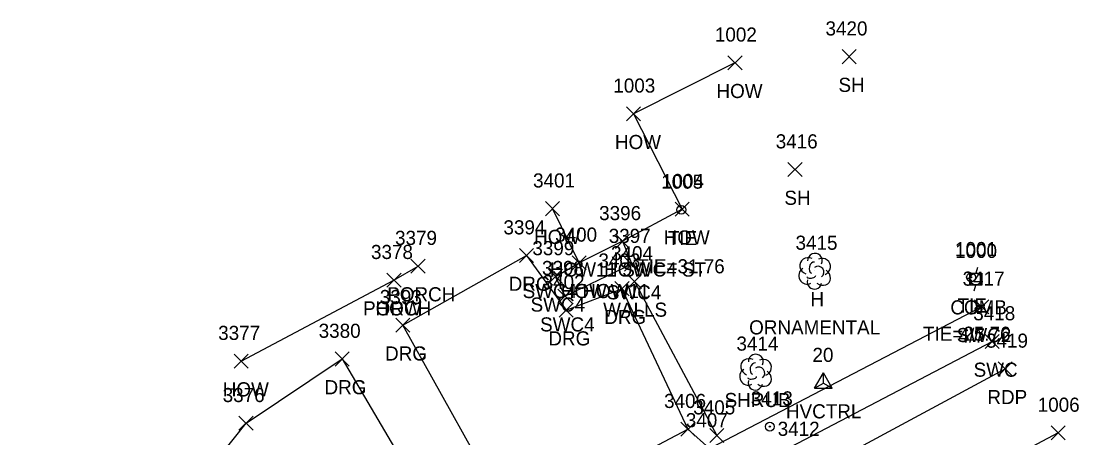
# Model space of a CAD drawing. Extents: x 1477930 to 1480780, y 774090 to 784647.
# Drawn here: x 1479868.8 to 1480018.8, y 775005.2 to 775064.2 of the extents above; entities that cross this region are included whole.
import ezdxf

# ---------------------------------------------------------------- set-up
doc = ezdxf.new("R2010")
doc.units = 0
for name, color, linetype in [('C_A', 7, 'Continuous'), ('C_C', 7, 'Continuous'), ('C_I', 7, 'Continuous'), ('CBP', 7, 'Continuous'), ('CPSM', 7, 'Continuous'), ('L_A', 7, 'Continuous'), ('L_C', 7, 'Continuous'), ('L_I', 7, 'Continuous'), ('L_TIC', 7, 'Continuous'), ('LBC', 7, 'Continuous'), ('LBF', 7, 'Continuous'), ('LSH', 7, 'Continuous'), ('LTD', 7, 'Continuous'), ('LWS', 7, 'Continuous'), ('P_A', 7, 'Continuous'), ('P_I', 7, 'Continuous'), ('P_TIC', 7, 'Continuous'), ('PET', 7, 'Continuous'), ('PRC', 7, 'Continuous'), ('R_A', 7, 'Continuous'), ('R_I', 7, 'Continuous'), ('R_TIC', 7, 'Continuous'), ('RDG', 7, 'Continuous'), ('RDP', 7, 'Continuous'), ('RSW', 7, 'Continuous'), ('U_A', 7, 'Continuous'), ('U_C', 7, 'Continuous'), ('U_I', 7, 'Continuous'), ('UP', 7, 'Continuous'), ('UWV', 7, 'Continuous')]:
    doc.layers.add(name, color=color, linetype=linetype)

msp = doc.modelspace()

# ---------------------------------------------------------------- linework, layer by layer
at = {"layer": 'CBP'}
for centre, radius in [((1479962.44, 775037.49), 0.625), ((1479962.44, 775037.49), 0.0833), ((1480003.53, 775027.93), 0.625), ((1480003.53, 775027.93), 0.0833)]:
    msp.add_circle(centre, radius, dxfattribs=at)
at = {"layer": 'CPSM'}
for p, q in [((1479981.34, 775012.21), (1479982.59, 775014.37)), ((1479983.84, 775012.21), (1479982.59, 775014.37)), ((1479982.59, 775012.93), (1479982.59, 775014.37)), ((1479981.34, 775012.21), (1479982.59, 775012.93)), ((1479981.34, 775012.21), (1479983.84, 775012.21)), ((1479982.59, 775012.93), (1479982.59, 775012.93)), ((1479982.59, 775012.93), (1479983.84, 775012.21))]:
    msp.add_line(p, q, dxfattribs=at)
at = {"layer": 'L_TIC'}
for points in [[(1479985.24, 775058.21), (1479987.24, 775060.21)], [(1479987.24, 775058.21), (1479985.24, 775060.21)], [(1479969.05, 775057.34), (1479971.05, 775059.34)], [(1479971.05, 775057.34), (1479969.05, 775059.34)], [(1479954.65, 775050.11), (1479956.65, 775052.11)], [(1479956.65, 775050.11), (1479954.65, 775052.11)], [(1479977.57, 775042.2), (1479979.57, 775044.2)], [(1479979.57, 775042.2), (1479977.57, 775044.2)], [(1479943.19, 775036.66), (1479945.19, 775038.66)], [(1479945.19, 775036.66), (1479943.19, 775038.66)], [(1479961.55, 775036.58), (1479963.55, 775038.58)], [(1479963.55, 775036.58), (1479961.55, 775038.58)], [(1479961.55, 775036.58), (1479963.55, 775038.58)], [(1479963.55, 775036.58), (1479961.55, 775038.58)], [(1479953.1, 775032.03), (1479955.1, 775034.03)], [(1479955.1, 775032.03), (1479953.1, 775034.03)], [(1479924.11, 775028.52), (1479926.11, 775030.52)], [(1479926.11, 775028.52), (1479924.11, 775030.52)], [(1479946.97, 775028.98), (1479948.97, 775030.98)], [(1479948.97, 775028.98), (1479946.97, 775030.98)], [(1479920.7, 775026.52), (1479922.7, 775028.52)], [(1479922.7, 775026.52), (1479920.7, 775028.52)], [(1479920.7, 775026.52), (1479922.7, 775028.52)], [(1479922.7, 775026.52), (1479920.7, 775028.52)], [(1479954.82, 775026.34), (1479956.82, 775028.34)], [(1479956.82, 775026.34), (1479954.82, 775028.34)], [(1479899.03, 775015.05), (1479901.03, 775017.05)], [(1479901.03, 775015.05), (1479899.03, 775017.05)], [(1479966.48, 775004.49), (1479968.48, 775006.49)], [(1479968.48, 775004.49), (1479966.48, 775006.49)]]:
    msp.add_lwpolyline(points, dxfattribs=at)
at = {"layer": 'LBC'}
for points in [[(1479970.05, 775058.34), (1479955.65, 775051.11), (1479962.55, 775037.58)], [(1479962.55, 775037.58), (1479954.1, 775033.03), (1479947.97, 775029.98), (1479944.19, 775037.66)], [(1479900.03, 775016.05), (1479921.7, 775027.52)]]:
    msp.add_lwpolyline(points, dxfattribs=at)
at = {"layer": 'LBF'}
msp.add_lwpolyline([(1479921.7, 775027.52), (1479925.11, 775029.52)], dxfattribs=at)
at = {"layer": 'LSH'}
msp.add_line((1479972.95, 775014.53), (1479972.95, 775014.53), dxfattribs=at)
msp.add_line((1479972.95, 775014.53), (1479972.95, 775014.53), dxfattribs=at)
msp.add_arc((1479973, 775015.97), 1.05, 335.5272, 180.9563, dxfattribs=at)
for centre, major_axis, ratio, start_param, end_param in [((1479972.16, 775015.2), (1.21, -0.51), 0.895232, 1.570796, 4.712389), ((1479972.74, 775014.99), (-0.208, -0.792), 0.645439, 3.141593, 6.283185), ((1479973.45, 775014.36), (-0.5, 0.667), 0.989748, 3.141593, 6.283185), ((1479973.99, 775015.12), (-1.14, -0.48), 0.949671, 1.570796, 4.712389), ((1479971.87, 775013.82), (0.58, -1.04), 0.959034, 3.141593, 6.283185), ((1479972.49, 775013.78), (-0.625, -0.083), 0.423636, 0, 3.141593), ((1479973.95, 775013.7), (-1.09, 0.79), 0.841452, 1.570796, 4.712389), ((1479972.95, 775013.03), (0.26, 1.06), 0.942809, 1.570796, 4.712389)]:
    msp.add_ellipse(centre, major_axis=major_axis, ratio=ratio, start_param=start_param, end_param=end_param, dxfattribs=at)
at = {"layer": 'LTD'}
msp.add_line((1479981.33, 775028.83), (1479981.33, 775028.83), dxfattribs=at)
msp.add_line((1479981.33, 775028.83), (1479981.33, 775028.83), dxfattribs=at)
msp.add_arc((1479981.38, 775030.27), 1.05, 335.5272, 180.9563, dxfattribs=at)
for centre, major_axis, ratio, start_param, end_param in [((1479980.54, 775029.5), (1.21, -0.51), 0.895232, 1.570796, 4.712389), ((1479981.12, 775029.29), (-0.208, -0.792), 0.645439, 3.141593, 6.283185), ((1479982.37, 775029.42), (-1.14, -0.48), 0.949671, 1.570796, 4.712389), ((1479980.25, 775028.13), (0.58, -1.04), 0.959034, 3.141593, 6.283185), ((1479981.83, 775028.67), (-0.5, 0.667), 0.989748, 3.141593, 6.283185), ((1479982.33, 775028), (-1.09, 0.79), 0.841452, 1.570796, 4.712389), ((1479981.33, 775027.33), (0.26, 1.06), 0.942809, 1.570796, 4.712389), ((1479980.87, 775028.08), (-0.625, -0.083), 0.423636, 0, 3.141593)]:
    msp.add_ellipse(centre, major_axis=major_axis, ratio=ratio, start_param=start_param, end_param=end_param, dxfattribs=at)
at = {"layer": 'LWS'}
msp.add_lwpolyline([(1479955.82, 775027.34), (1479967.48, 775005.49)], dxfattribs=at)
at = {"layer": 'P_TIC'}
for points in [[(1480007.35, 775013.95), (1480009.35, 775015.95)], [(1480009.35, 775013.95), (1480007.35, 775015.95)], [(1480014.89, 775004.87), (1480016.89, 775006.87)], [(1480016.89, 775004.87), (1480014.89, 775006.87)]]:
    msp.add_lwpolyline(points, dxfattribs=at)
at = {"layer": 'PET'}
msp.add_lwpolyline([(1479458.85, 774725.87), (1479463.75, 774725.49), (1479503.78, 774746.04), (1479529.26, 774759.88), (1479547.26, 774769.69), (1479593.15, 774794.19), (1479638.49, 774817.33), (1479672.22, 774835.12), (1479713.57, 774857.96), (1479753.19, 774879.74), (1479794.61, 774902.46), (1479830.33, 774920.88), (1479861.74, 774937.83), (1479877.76, 774946.85), (1479905.13, 774960.92), (1479936.65, 774977.61), (1479958.81, 774989.4), (1479973, 774995.93), (1480008.35, 775014.95)], dxfattribs=at)
at = {"layer": 'PRC'}
msp.add_lwpolyline([(1480015.89, 775005.87), (1479971.79, 774982.46), (1479929.14, 774959.03), (1479892.61, 774942.34), (1479860.44, 774925.31), (1479806.49, 774896.54), (1479658.45, 774815.54), (1479643.75, 774807.57), (1479597.62, 774782.97), (1479555.61, 774761.16), (1479513.42, 774740.32), (1479471, 774718.6), (1479432.73, 774701.1), (1479418.32, 774694.97), (1479344.83, 774660.92), (1479298.6, 774640.39), (1479262.12, 774624.4), (1479219.63, 774609.01), (1479186.74, 774593.83)], dxfattribs=at)
at = {"layer": 'R_TIC'}
for points in [[(1479953.1, 775032.03), (1479955.1, 775034.03)], [(1479955.1, 775032.03), (1479953.1, 775034.03)], [(1479939.48, 775030.01), (1479941.48, 775032.01)], [(1479941.48, 775030.01), (1479939.48, 775032.01)], [(1479946.97, 775028.98), (1479948.97, 775030.98)], [(1479948.97, 775028.98), (1479946.97, 775030.98)], [(1479954.41, 775028.8), (1479956.41, 775030.8)], [(1479956.41, 775028.8), (1479954.41, 775030.8)], [(1479943.59, 775027.06), (1479945.59, 775029.06)], [(1479945.59, 775027.06), (1479943.59, 775029.06)], [(1479953.03, 775025.31), (1479955.03, 775027.31)], [(1479955.03, 775025.31), (1479953.03, 775027.31)], [(1479944.95, 775024.25), (1479946.95, 775026.25)], [(1479946.95, 775024.25), (1479944.95, 775026.25)], [(1479945.11, 775022.27), (1479947.11, 775024.27)], [(1479947.11, 775022.27), (1479945.11, 775024.27)], [(1480004.03, 775022.74), (1480006.03, 775024.74)], [(1480006.03, 775022.74), (1480004.03, 775024.74)], [(1479921.95, 775020.13), (1479923.95, 775022.13)], [(1479923.95, 775020.13), (1479921.95, 775022.13)], [(1479921.95, 775020.13), (1479923.95, 775022.13)], [(1479923.95, 775020.13), (1479921.95, 775022.13)], [(1479921.95, 775020.13), (1479923.95, 775022.13)], [(1479923.95, 775020.13), (1479921.95, 775022.13)], [(1480005.53, 775017.83), (1480007.53, 775019.83)], [(1480007.53, 775017.83), (1480005.53, 775019.83)], [(1479913.36, 775015.35), (1479915.36, 775017.35)], [(1479915.36, 775015.35), (1479913.36, 775017.35)], [(1479913.36, 775015.35), (1479915.36, 775017.35)], [(1479915.36, 775015.35), (1479913.36, 775017.35)], [(1479913.36, 775015.35), (1479915.36, 775017.35)], [(1479915.36, 775015.35), (1479913.36, 775017.35)], [(1479899.72, 775006.24), (1479901.72, 775008.24)], [(1479901.72, 775006.24), (1479899.72, 775008.24)], [(1479962.39, 775005.4), (1479964.39, 775007.4)], [(1479964.39, 775005.4), (1479962.39, 775007.4)], [(1479962.39, 775005.4), (1479964.39, 775007.4)], [(1479964.39, 775005.4), (1479962.39, 775007.4)]]:
    msp.add_lwpolyline(points, dxfattribs=at)
at = {"layer": 'RDG'}
for points in [[(1479922.95, 775021.13), (1479940.48, 775031.01), (1479946.11, 775023.27), (1479954.03, 775026.31), (1479963.39, 775006.4)], [(1479880.81, 774958.36), (1479872.61, 774977.5), (1479892.08, 774996.39), (1479900.72, 775007.24), (1479914.36, 775016.35)]]:
    msp.add_lwpolyline(points, dxfattribs=at)
at = {"layer": 'RDP'}
for points in [[(1479914.36, 775016.35), (1479930.45, 774988.97), (1479938.49, 774993.27), (1479922.95, 775021.13)], [(1479938.49, 774993.27), (1479963.39, 775006.4), (1479966.42, 775003.67)]]:
    msp.add_lwpolyline(points, dxfattribs=at)
at = {"layer": 'RSW'}
for points in [[(1479954.1, 775033.03), (1479955.41, 775029.8), (1479945.95, 775025.25), (1479944.59, 775028.06), (1479947.97, 775029.98)], [(1479454.05, 774732.2), (1479457.36, 774735.51), (1479461.55, 774734.41), (1479499.97, 774753.7), (1479531.62, 774770.46), (1479545.78, 774777.94), (1479596.7, 774804.86), (1479626.34, 774821.05), (1479665.84, 774842.34), (1479709.72, 774866.29), (1479748.23, 774887.23), (1479790.98, 774910.55), (1479825.88, 774929.42), (1479857.89, 774946.35), (1479880.81, 774958.36), (1479898.02, 774967.81), (1479932.31, 774985.56), (1479966.42, 775003.67), (1480005.03, 775023.74)], [(1479458.85, 774725.87), (1479459.6, 774730), (1479502.04, 774749.23), (1479530.65, 774764.31), (1479546.64, 774772.58), (1479592.5, 774796.78), (1479632.83, 774818.63), (1479668.4, 774838.36), (1479711.89, 774862.21), (1479750.54, 774883.44), (1479792.95, 774906.12), (1479828.15, 774924.96), (1479859.81, 774941.82), (1479882.29, 774953.43), (1479899.45, 774962.93), (1479935.39, 774981.77), (1479958.84, 774993.68), (1479967.68, 774998.52), (1480006.53, 775018.83)]]:
    msp.add_lwpolyline(points, dxfattribs=at)
at = {"layer": 'UP'}
for p, q in [((1480004.45, 775029.33), (1480004.2, 775028.5)), ((1480003.37, 775026.83), (1480003.37, 775028.5)), ((1480003.37, 775028.5), (1480005.04, 775028.5)), ((1480004.2, 775027.67), (1480004.2, 775027.67)), ((1480005.04, 775028.5), (1480005.04, 775026.83)), ((1480005.04, 775026.83), (1480003.37, 775026.83)), ((1480003.95, 775026), (1480004.2, 775026.83))]:
    msp.add_line(p, q, dxfattribs=at)
msp.add_circle((1480004.2, 775027.67), 0.833, dxfattribs=at)
at = {"layer": 'UWV'}
for radius in [0.625, 0.0833]:
    msp.add_circle((1479975, 775006.76), radius, dxfattribs=at)

# ---------------------------------------------------------------- texts
at = {"layer": 'C_A'}
for s, p in [('TIE', (1479960.52, 775032.49)), ('TIE', (1480001.61, 775022.93)), ('HVCTRL', (1479977.28, 775007.93))]:
    msp.add_text(s, height=2, dxfattribs=at).set_placement(p)
at = {"layer": 'C_C'}
for s, p in [('TIE=31.76', (1479956.18, 775028.49)), ('TIE=25.76', (1479996.71, 775018.93))]:
    msp.add_text(s, height=2, dxfattribs=at).set_placement(p)
at = {"layer": 'C_I'}
for s, p in [('1005', (1479959.59, 775040.49)), ('1001', (1480001.25, 775030.93)), ('20', (1479981.04, 775015.93))]:
    msp.add_text(s, height=2, dxfattribs=at).set_placement(p)
at = {"layer": 'L_A'}
for s, p in [('SH', (1479984.73, 775054.21)), ('HOW', (1479967.43, 775053.34)), ('HOW', (1479953.03, 775046.11)), ('SH', (1479977.06, 775038.2)), ('HOW', (1479941.57, 775032.66)), ('HOW', (1479959.94, 775032.58)), ('HOW', (1479959.94, 775032.58)), ('HOW', (1479951.49, 775028.03)), ('PORCH', (1479920.74, 775024.52)), ('HOW', (1479945.36, 775024.98)), ('H', (1479980.76, 775023.83)), ('PORCH', (1479917.32, 775022.52)), ('HOW', (1479919.08, 775022.52)), ('WALLS', (1479951.36, 775022.34)), ('HOW', (1479897.42, 775011.05)), ('SHRUB', (1479968.58, 775009.53))]:
    msp.add_text(s, height=2, dxfattribs=at).set_placement(p)
at = {"layer": 'L_C'}
msp.add_text('ORNAMENTAL', height=2, dxfattribs=at).set_placement((1479972.06, 775019.83))
at = {"layer": 'L_I'}
for s, p in [('1002', (1479967.2, 775061.34)), ('3420', (1479982.89, 775062.21)), ('1003', (1479952.8, 775054.11)), ('3416', (1479975.83, 775046.2)), ('3401', (1479941.42, 775040.66)), ('1004', (1479959.7, 775040.58)), ('1004', (1479959.7, 775040.58)), ('3396', (1479950.79, 775036.03)), ('3379', (1479921.85, 775032.52)), ('3400', (1479944.55, 775032.98)), ('3415', (1479978.64, 775031.83)), ('3378', (1479918.44, 775030.52)), ('3378', (1479918.44, 775030.52)), ('3404', (1479952.48, 775030.34)), ('3377', (1479896.77, 775019.05)), ('3414', (1479970.26, 775017.53)), ('3405', (1479964.14, 775008.49)), ('3412', (1479976.11, 775005.45))]:
    msp.add_text(s, height=2, dxfattribs=at).set_placement(p)
at = {"layer": 'P_A'}
msp.add_text('RDP', height=2, dxfattribs=at).set_placement((1480005.84, 775009.95))
at = {"layer": 'P_I'}
for s, p in [('3419', (1480005.65, 775017.95)), ('1006', (1480012.98, 775008.87))]:
    msp.add_text(s, height=2, dxfattribs=at).set_placement(p)
at = {"layer": 'R_A'}
for s, p in [('HOW11 SWC4 ST', (1479943.81, 775028.03)), ('DRG', (1479937.96, 775026.01)), ('SWC4 HOW11', (1479939.94, 775024.98)), ('SWC4', (1479951.88, 775024.8)), ('SWC4', (1479941.07, 775023.06)), ('DRG', (1479951.52, 775021.31)), ('SWC4', (1479942.42, 775020.25)), ('DRG', (1479943.59, 775018.27)), ('SWC2', (1480001.5, 775018.74)), ('DRC', (1479920.44, 775016.13)), ('DRC', (1479920.44, 775016.13)), ('DRG', (1479920.44, 775016.13)), ('SWC', (1480003.89, 775013.83)), ('DRG', (1479911.85, 775011.35)), ('DRC', (1479911.85, 775011.35)), ('DRG', (1479911.85, 775011.35))]:
    msp.add_text(s, height=2, dxfattribs=at).set_placement(p)
at = {"layer": 'R_I'}
for s, p in [('3396', (1479950.79, 775036.03)), ('3394', (1479937.22, 775034.01)), ('3400', (1479944.55, 775032.98)), ('3397', (1479952.15, 775032.8)), ('3399', (1479941.32, 775031.06)), ('3398', (1479942.69, 775028.25)), ('3403', (1479950.69, 775029.31)), ('3417', (1480002.33, 775026.74)), ('3402', (1479942.77, 775026.27)), ('3393', (1479919.69, 775024.13)), ('3393', (1479919.69, 775024.13)), ('3393', (1479919.69, 775024.13)), ('3418', (1480003.84, 775021.83)), ('3380', (1479911.02, 775019.35)), ('3380', (1479911.02, 775019.35)), ('3380', (1479911.02, 775019.35)), ('3376', (1479897.41, 775010.24)), ('3406', (1479960, 775009.4)), ('3406', (1479960, 775009.4)), ('3407', (1479963.08, 775006.67)), ('3407', (1479963.08, 775006.67))]:
    msp.add_text(s, height=2, dxfattribs=at).set_placement(p)
at = {"layer": 'U_A'}
msp.add_text('COMB', height=2, dxfattribs=at).set_placement((1480000.59, 775022.67))
at = {"layer": 'U_C'}
msp.add_text('4/7', height=2, dxfattribs=at).set_placement((1480001.76, 775018.67))
at = {"layer": 'U_I'}
for s, p in [('1000', (1480001.26, 775030.67)), ('3413', (1479972.3, 775009.76))]:
    msp.add_text(s, height=2, dxfattribs=at).set_placement(p)

doc.saveas('drawing.dxf')
